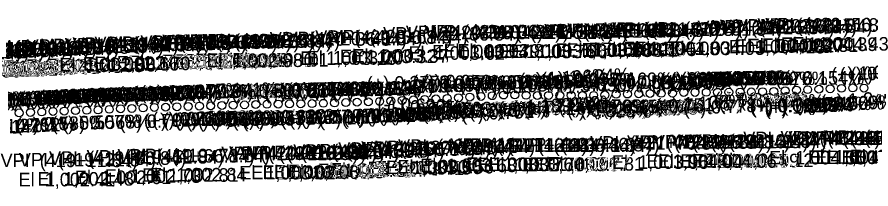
# Model space of a CAD drawing. Extents: x 16972137 to 16976972, y 12558490 to 12559551.
# Drawn here: x 16976278.8 to 16976657.8, y 12558916.8 to 12558992.8 of the extents above; entities that cross this region are included whole.
import ezdxf

# ---------------------------------------------------------------- set-up
doc = ezdxf.new("R2010")
doc.units = 0
doc.layers.add('RD_DDB_GradeTX', color=7, linetype='Continuous')
doc.layers.add('RD_DDB_PI', color=7, linetype='Continuous')

msp = doc.modelspace()

# ---------------------------------------------------------------- linework, layer by layer
at = {"layer": 'RD_DDB_PI'}
for centre in [(16976499.74, 12558958.35), (16976544.74, 12558958.62), (16976549.74, 12558958.74), (16976554.74, 12558958.85), (16976559.74, 12558958.96), (16976564.74, 12558959.04), (16976569.74, 12558959.11), (16976574.74, 12558959.45), (16976579.74, 12558959.47), (16976584.74, 12558959.49), (16976589.74, 12558959.51), (16976594.74, 12558959.56), (16976599.74, 12558959.59), (16976604.74, 12558959.68), (16976609.74, 12558959.79), (16976614.74, 12558959.91), (16976619.74, 12558960.22), (16976624.74, 12558960.48), (16976629.74, 12558960.68), (16976634.74, 12558960.88), (16976639.74, 12558961.08), (16976644.74, 12558961.27), (16976649.74, 12558961.46), (16976654.74, 12558961.37), (16976414.74, 12558954.64), (16976419.74, 12558954.78), (16976424.74, 12558954.95), (16976429.74, 12558955.13), (16976434.74, 12558955.3), (16976439.74, 12558955.47), (16976444.74, 12558955.67), (16976449.74, 12558955.93), (16976454.74, 12558956.15), (16976459.74, 12558956.36), (16976464.74, 12558956.58), (16976469.74, 12558956.79), (16976474.74, 12558957.09), (16976479.74, 12558957.39), (16976484.74, 12558957.69), (16976489.74, 12558958), (16976494.74, 12558958.29), (16976504.74, 12558958.18), (16976509.74, 12558958.1), (16976514.74, 12558958.11), (16976519.74, 12558958.13), (16976524.74, 12558958.12), (16976529.74, 12558958.09), (16976534.74, 12558958.15), (16976539.74, 12558958.34), (16976289.74, 12558950.83), (16976294.74, 12558951.03), (16976299.74, 12558951.2), (16976304.74, 12558951.38), (16976309.74, 12558951.58), (16976314.74, 12558951.7), (16976319.74, 12558951.96), (16976324.74, 12558952.21), (16976329.74, 12558952.38), (16976334.74, 12558952.6), (16976339.74, 12558952.81), (16976344.74, 12558952.94), (16976349.74, 12558953.11), (16976354.74, 12558953.26), (16976359.74, 12558953.39), (16976364.74, 12558953.53), (16976369.74, 12558953.68), (16976374.74, 12558953.83), (16976379.74, 12558953.96), (16976384.74, 12558954.1), (16976389.74, 12558954.2), (16976394.74, 12558954.3), (16976399.74, 12558954.37), (16976404.74, 12558954.44), (16976409.74, 12558954.53), (16976279.74, 12558950.37), (16976284.74, 12558950.61)]:
    msp.add_circle(centre, 1.75, dxfattribs=at)

# ---------------------------------------------------------------- texts
at = {"layer": 'RD_DDB_GradeTX'}
for s, rotation, p in [('(+) 1.040%', 2.9768, (16976640.33, 12558964.3)), ('(+) 0.798%', 2.2855, (16976644.02, 12558964.26)), ('(+) 0.788%', 2.2566, (16976648.9, 12558964.44)), ('(+) 0.778%', 2.2276, (16976654.2, 12558964.64)), ('(+) 1.196%', 3.4227, (16976502.06, 12558961.74)), ('(+) 1.124%', 3.2161, (16976511.72, 12558962.24)), ('(+) 0.092%', 0.2624, (16976513.61, 12558962.17)), ('(+) 0.277%', 0.7937, (16976514.05, 12558961.55)), ('(+) 0.169%', 0.4835, (16976530.6, 12558962.01)), ('(+) 1.040%', 2.9768, (16976560.44, 12558960.15)), ('(+) 0.798%', 2.2855, (16976564.08, 12558961.07)), ('(+) 0.470%', 1.3471, (16976564.07, 12558962.08)), ('(+) 0.448%', 1.2819, (16976568.9, 12558962.17)), ('(+) 0.788%', 2.2566, (16976568.97, 12558961.29)), ('(+) 0.425%', 1.2167, (16976573.43, 12558962.25)), ('(+) 0.358%', 1.0258, (16976578.27, 12558962.29)), ('(+) 0.787%', 2.2525, (16976579.26, 12558961.7)), ('(+) 0.265%', 0.7604, (16976583.46, 12558962.29)), ('(+) 0.740%', 2.12, (16976584.08, 12558962.03)), ('(+) 0.092%', 0.2624, (16976593.61, 12558962.53)), ('(+) 0.076%', 0.2168, (16976599.14, 12558962.54)), ('(+) 0.154%', 0.4413, (16976615.37, 12558962.71)), ('(+) 0.841%', 2.4083, (16976355.36, 12558956.47)), ('(+) 0.863%', 2.4706, (16976388.49, 12558956.29)), ('(+) 0.572%', 1.6372, (16976388.58, 12558957.22)), ('(+) 0.551%', 1.5767, (16976395.06, 12558957.39)), ('(+) 0.548%', 1.5691, (16976398.65, 12558957.48)), ('(+) 0.400%', 1.1454, (16976403.79, 12558957.48)), ('(+) 0.391%', 1.1187, (16976410.15, 12558957.6)), ('(+) 0.284%', 0.8126, (16976413.57, 12558957.57)), ('(+) 1.211%', 3.465, (16976418.39, 12558956.69)), ('(+) 0.268%', 0.7673, (16976418.58, 12558957.62)), ('(+) 1.242%', 3.5532, (16976424.98, 12558956.99)), ('(+) 1.124%', 3.2161, (16976431.86, 12558957.76)), ('(+) 0.277%', 0.7937, (16976434.06, 12558960.44)), ('(+) 0.684%', 1.9574, (16976448.86, 12558958.79)), ('(+) 0.657%', 1.8825, (16976453.92, 12558958.93)), ('(+) 0.067%', 0.1931, (16976454.14, 12558960.91)), ('(-) 0.056%', 359.8391, (16976458.75, 12558961.3)), ('(+) 0.863%', 2.4706, (16976468.41, 12558959.74)), ('(+) 0.851%', 2.4373, (16976475.13, 12558960.02)), ('(+) 1.108%', 3.1702, (16976481.97, 12558958.15)), ('(+) 0.470%', 1.3471, (16976484.1, 12558960.19)), ('(+) 0.448%', 1.2819, (16976488.92, 12558960.38)), ('(+) 0.425%', 1.2167, (16976493.45, 12558960.55)), ('(+) 0.358%', 1.0258, (16976498.28, 12558960.86)), ('(+) 1.342%', 3.84, (16976509.92, 12558958.1)), ('(-) 0.690%', 358.0253, (16976519.07, 12558960.69)), ('(-) 0.056%', 359.8391, (16976538.75, 12558961.08)), ('(-) 0.088%', 359.7485, (16976543.75, 12558961.03)), ('(+) 1.245%', 3.5629, (16976555.09, 12558959.21)), ('(+) 1.398%', 3.9989, (16976244.95, 12558951.58)), ('(+) 1.271%', 3.6374, (16976266.87, 12558952.8)), ('(+) 0.850%', 2.4346, (16976268.55, 12558952.79)), ('(+) 1.245%', 3.5625, (16976269.93, 12558952.97)), ('(+) 0.841%', 2.4083, (16976275.44, 12558953.11)), ('(+) 1.191%', 3.407, (16976278.6, 12558953.45)), ('(+) 1.104%', 3.1607, (16976281.96, 12558953.55)), ('(+) 0.690%', 1.9757, (16976283.91, 12558953.84)), ('(+) 1.100%', 3.147, (16976286.85, 12558953.81)), ('(+) 0.586%', 1.6795, (16976288.68, 12558954.32)), ('(+) 1.015%', 2.9063, (16976291.75, 12558953.99)), ('(+) 0.983%', 2.8136, (16976293.39, 12558954.04)), ('(+) 0.953%', 2.7275, (16976298.28, 12558954.25)), ('(+) 0.620%', 1.7751, (16976303.56, 12558954.63)), ('(+) 0.915%', 2.619, (16976305.23, 12558954.55)), ('(+) 0.572%', 1.6372, (16976308.62, 12558954.94)), ('(+) 0.768%', 2.1989, (16976309.02, 12558954.58)), ('(+) 0.703%', 2.0127, (16976313.62, 12558954.69)), ('(+) 0.551%', 1.5767, (16976315.1, 12558955.19)), ('(+) 0.548%', 1.5691, (16976318.68, 12558955.29)), ('(+) 0.698%', 1.9992, (16976318.86, 12558954.87)), ('(+) 0.400%', 1.1454, (16976323.81, 12558955.88)), ('(+) 0.391%', 1.1187, (16976330.17, 12558956.04)), ('(+) 0.514%', 1.4734, (16976330.31, 12558955.11)), ('(+) 0.284%', 0.8126, (16976333.58, 12558956.43)), ('(+) 0.977%', 2.7964, (16976339.28, 12558955.92)), ('(+) 0.712%', 2.038, (16976345.33, 12558955.94)), ('(+) 0.535%', 1.5325, (16976358.12, 12558956.3)), ('(+) 0.736%', 2.1075, (16976363.79, 12558955.71)), ('(+) 0.586%', 1.6795, (16976368.64, 12558956.67)), ('(+) 0.684%', 1.9574, (16976368.91, 12558956.05)), ('(+) 0.507%', 1.4514, (16976373.83, 12558956.74)), ('(+) 1.022%', 2.9245, (16976384.85, 12558955.62)), ('(+) 1.245%', 3.5629, (16976635.67, 12558952.2)), ('(+) 0.792%', 2.2674, (16976243.85, 12558951.97)), ('(+) 1.117%', 3.1973, (16976253.79, 12558951.85)), ('(+) 1.033%', 2.9562, (16976254.73, 12558951.61)), ('(+) 0.977%', 2.7964, (16976259.38, 12558952.02)), ('(-) 0.690%', 358.0253, (16976438.7, 12558951.45)), ('(-) 0.325%', 359.0691, (16976442.95, 12558950.19)), ('(+) 1.189%', 3.4011, (16976492.66, 12558949.14)), ('(+) 1.211%', 3.465, (16976498.96, 12558949.54)), ('(+) 1.242%', 3.5532, (16976505.56, 12558949.97)), ('(+) 0.076%', 0.2168, (16976519.19, 12558950.24)), ('(+) 0.099%', 0.2848, (16976524.02, 12558950.19)), ('(+) 0.154%', 0.4413, (16976535.46, 12558950.1)), ('(+) 0.751%', 2.1499, (16976555.89, 12558949.94)), ('(+) 1.108%', 3.1702, (16976562.51, 12558950.59)), ('(+) 0.778%', 2.2276, (16976574.73, 12558949.54)), ('(-) 0.345%', 359.0114, (16976588.3, 12558953.52)), ('(+) 1.342%', 3.84, (16976590.53, 12558951.49)), ('(-) 0.330%', 359.0559, (16976593.01, 12558953.39)), ('(-) 0.313%', 359.1044, (16976599.67, 12558953.23)), ('(+) 0.099%', 0.2848, (16976604.02, 12558950.58)), ('(+) 0.704%', 2.0164, (16976604.51, 12558950.08)), ('(+) 1.028%', 2.9425, (16976610.7, 12558949.34)), ('(+) 0.169%', 0.4835, (16976610.7, 12558950.69)), ('(+) 0.362%', 1.0383, (16976618.48, 12558950.93)), ('(+) 0.406%', 1.1637, (16976624.15, 12558951.08)), ('(+) 0.509%', 1.4584, (16976628.96, 12558951.27)), ('(+) 0.877%', 2.51, (16976404.78, 12558944.94)), ('(+) 1.189%', 3.4011, (16976412.81, 12558944.4)), ('(+) 1.196%', 3.4227, (16976422.93, 12558944.98)), ('(+) 0.392%', 1.1218, (16976423.5, 12558945.8)), ('(+) 0.403%', 1.1545, (16976428.74, 12558945.92)), ('(+) 0.580%', 1.6604, (16976433.87, 12558946.19)), ('(+) 0.665%', 1.9052, (16976439.14, 12558946.42)), ('(+) 0.736%', 2.1075, (16976444.17, 12558946.66)), ('(+) 0.045%', 0.1295, (16976448.76, 12558948.96)), ('(+) 0.835%', 2.3896, (16976458.68, 12558947.25)), ('(-) 0.088%', 359.7485, (16976463.7, 12558949.38)), ('(+) 1.022%', 2.9245, (16976465.35, 12558947.72)), ('(+) 0.248%', 0.709, (16976468.74, 12558948.34)), ('(+) 0.751%', 2.1499, (16976475.95, 12558946.94)), ('(+) 0.870%', 2.4914, (16976479.41, 12558948.21)), ('(+) 0.877%', 2.51, (16976484.7, 12558948.44)), ('(+) 0.265%', 0.7604, (16976503.63, 12558949.23)), ('(-) 0.325%', 359.0691, (16976522.94, 12558948.89)), ('(+) 0.045%', 0.1295, (16976528.76, 12558949.14)), ('(+) 0.067%', 0.1931, (16976534.18, 12558949.18)), ('(+) 0.362%', 1.0383, (16976538.5, 12558949.48)), ('(+) 0.406%', 1.1637, (16976544.17, 12558949.45)), ('(+) 0.248%', 0.709, (16976548.73, 12558949.33)), ('(+) 0.509%', 1.4584, (16976548.99, 12558949.24)), ('(+) 1.276%', 3.6497, (16976261.1, 12558940.42)), ('(+) 0.535%', 1.5325, (16976278.47, 12558942.16)), ('(+) 0.507%', 1.4514, (16976294.16, 12558942.72)), ('(+) 0.568%', 1.626, (16976299.02, 12558942.66)), ('(+) 0.792%', 2.2674, (16976324.26, 12558943.14)), ('(+) 1.033%', 2.9562, (16976335.24, 12558943.75)), ('(+) 0.268%', 0.7673, (16976338.75, 12558944.55)), ('(+) 0.392%', 1.1218, (16976343.51, 12558944.24)), ('(+) 0.403%', 1.1545, (16976348.75, 12558944.3)), ('(+) 0.850%', 2.4346, (16976348.98, 12558944.19)), ('(+) 0.580%', 1.6604, (16976353.91, 12558943.87)), ('(+) 0.665%', 1.9052, (16976359.19, 12558943.76)), ('(+) 0.690%', 1.9757, (16976364.27, 12558944.61)), ('(+) 0.657%', 1.8825, (16976374.36, 12558944.31)), ('(+) 0.835%', 2.3896, (16976378.76, 12558943.91)), ('(+) 0.568%', 1.626, (16976378.99, 12558944.93)), ('(+) 0.620%', 1.7751, (16976383.89, 12558945.12)), ('(+) 0.851%', 2.4373, (16976395.71, 12558944.62)), ('(+) 0.870%', 2.4914, (16976399.49, 12558944.73)), ('(+) 0.514%', 1.4734, (16976250.64, 12558941.05)), ('(+) 1.142%', 3.2679, (16976257.4, 12558940.07)), ('(+) 0.712%', 2.038, (16976265.81, 12558941.1))]:
    msp.add_text(s, height=6, rotation=rotation, dxfattribs=at).set_placement(p)
at = {"layer": 'RD_DDB_PI'}
for s, p in [('VPI  (421+81.84)', (16976539.46, 12558984.45)), ('VPI  (421+86.84)', (16976542.92, 12558984.47)), ('VPI  (422+01.84)', (16976557.57, 12558984.56)), ('VPI  (422+26.84)', (16976580.79, 12558985.22)), ('VPI  (422+31.84)', (16976587.27, 12558985.48)), ('VPI  (422+36.84)', (16976590.74, 12558985.68)), ('VPI  (422+41.84)', (16976597.68, 12558985.88)), ('VPI  (422+51.84)', (16976607.45, 12558986.27)), ('VPI  (422+56.84)', (16976610.91, 12558986.46)), ('VPI  (420+56.84)', (16976411.15, 12558980.93)), ('VPI  (420+61.84)', (16976417.92, 12558981.15)), ('VPI  (420+86.84)', (16976441.27, 12558982.39)), ('VPI  (420+96.84)', (16976451.39, 12558983)), ('VPI  (421+01.84)', (16976459.46, 12558983.29)), ('VPI  (421+06.84)', (16976462.92, 12558983.35)), ('VPI  (421+26.84)', (16976482.68, 12558983.13)), ('VPI  (421+31.84)', (16976489.16, 12558983.12)), ('VPI  (421+51.84)', (16976509.34, 12558983.62)), ('VPI  (421+56.84)', (16976512.8, 12558983.74)), ('VPI  (421+61.84)', (16976519.57, 12558983.85)), ('VPI  (421+66.84)', (16976523.04, 12558983.96)), ('VPI  (421+71.84)', (16976529.75, 12558984.04)), ('VPI  (419+16.84)', (16976274.93, 12558976.58)), ('VPI  (419+26.84)', (16976283.04, 12558976.96)), ('VPI  (419+31.84)', (16976289.51, 12558977.21)), ('VPI  (419+41.84)', (16976299.93, 12558977.6)), ('VPI  (419+46.84)', (16976303.39, 12558977.81)), ('VPI  (419+56.84)', (16976313.16, 12558978.11)), ('VPI  (419+61.84)', (16976319.93, 12558978.26)), ('VPI  (419+76.84)', (16976333.57, 12558978.68)), ('VPI  (419+81.84)', (16976339.81, 12558978.83)), ('VPI  (419+86.84)', (16976343.27, 12558978.96)), ('VPI  (419+91.84)', (16976349.93, 12558979.1)), ('VPI  (419+96.84)', (16976353.39, 12558979.2)), ('VPI  (420+01.84)', (16976357.8, 12558979.3)), ('VPI  (420+06.84)', (16976361.27, 12558979.37)), ('VPI  (420+36.84)', (16976390.97, 12558980.13)), ('VPI  (420+41.84)', (16976397.92, 12558980.3)), ('El  1,004.18', (16976594.73, 12558976.72)), ('El  1,004.23', (16976597.55, 12558976.98)), ('El  1,004.27', (16976603.11, 12558977.18)), ('El  1,004.31', (16976609.41, 12558977.38)), ('El  1,004.39', (16976617.87, 12558977.77)), ('El  1,004.43', (16976622.9, 12558977.96)), ('VPI  (418+61.84)', (16976219.81, 12558974.02)), ('VPI  (418+66.84)', (16976223.27, 12558974.32)), ('VPI  (418+71.84)', (16976229.99, 12558974.59)), ('VPI  (418+76.84)', (16976233.45, 12558974.87)), ('VPI  (418+81.84)', (16976239.69, 12558975.12)), ('VPI  (418+86.84)', (16976243.16, 12558975.37)), ('VPI  (418+91.84)', (16976249.81, 12558975.61)), ('VPI  (418+96.84)', (16976253.27, 12558975.83)), ('VPI  (419+01.84)', (16976259.81, 12558976.03)), ('VPI  (419+06.84)', (16976263.27, 12558976.2)), ('El  1,003.62', (16976452.55, 12558973.89)), ('El  1,003.74', (16976463.05, 12558974.5)), ('El  1,003.79', (16976468.05, 12558974.79)), ('El  1,003.81', (16976474.29, 12558974.85)), ('El  1,003.76', (16976493.05, 12558974.63)), ('El  1,003.76', (16976498.05, 12558974.62)), ('El  1,003.86', (16976517.75, 12558975.12)), ('El  1,003.88', (16976522.66, 12558975.24)), ('El  1,003.91', (16976529.41, 12558975.35)), ('El  1,003.93', (16976532.49, 12558975.46)), ('El  1,003.95', (16976537.66, 12558975.54)), ('El  1,004.03', (16976547.78, 12558975.95)), ('El  1,004.03', (16976552.78, 12558975.97)), ('El  1,004.05', (16976567.96, 12558976.06)), ('El  1,002.66', (16976307.93, 12558969.1)), ('El  1,002.70', (16976312.99, 12558969.31)), ('El  1,002.76', (16976323.11, 12558969.61)), ('El  1,002.79', (16976328.11, 12558969.76)), ('El  1,002.87', (16976342.99, 12558970.18)), ('El  1,002.90', (16976347.81, 12558970.33)), ('El  1,002.93', (16976352.55, 12558970.46)), ('El  1,002.96', (16976357.93, 12558970.6)), ('El  1,002.98', (16976362.84, 12558970.7)), ('El  1,003.00', (16976367.64, 12558970.8)), ('El  1,003.01', (16976374.29, 12558970.87)), ('El  1,003.16', (16976404.41, 12558971.63)), ('El  1,003.20', (16976407.4, 12558971.8)), ('El  1,003.32', (16976422.13, 12558972.43)), ('El  1,003.37', (16976427.64, 12558972.65)), ('El  1,002.06', (16976237.81, 12558966.09)), ('El  1,002.11', (16976246, 12558966.37)), ('El  1,002.16', (16976249.47, 12558966.62)), ('El  1,002.21', (16976254.11, 12558966.87)), ('El  1,002.26', (16976257.58, 12558967.11)), ('El  1,002.30', (16976262.4, 12558967.33)), ('El  1,002.34', (16976267.52, 12558967.53)), ('El  1,002.38', (16976272.43, 12558967.7)), ('El  1,002.45', (16976282.72, 12558968.08)), ('El  1,002.53', (16976292.31, 12558968.46)), ('El  1,002.58', (16976297.61, 12558968.71)), ('VPI  (422+21.84)', (16976577.33, 12558934.91)), ('VPI  (422+46.84)', (16976601.15, 12558936.08)), ('VPI  (422+61.84)', (16976617.68, 12558936.37)), ('VPI  (422+66.84)', (16976621.15, 12558936.29)), ('VPI  (422+71.84)', (16976627.86, 12558936.21)), ('VPI  (422+76.84)', (16976631.33, 12558936.39)), ('VPI  (422+81.84)', (16976637.57, 12558936.64)), ('VPI  (420+66.84)', (16976421.39, 12558931.36)), ('VPI  (420+71.84)', (16976428.1, 12558931.58)), ('VPI  (420+76.84)', (16976431.56, 12558931.79)), ('VPI  (420+81.84)', (16976437.8, 12558932.09)), ('VPI  (420+91.84)', (16976447.92, 12558932.69)), ('VPI  (421+11.84)', (16976471.11, 12558933.18)), ('VPI  (421+16.84)', (16976474.57, 12558933.1)), ('VPI  (421+21.84)', (16976479.22, 12558933.11)), ('VPI  (421+36.84)', (16976492.63, 12558933.09)), ('VPI  (421+41.84)', (16976499.57, 12558933.15)), ('VPI  (421+46.84)', (16976503.04, 12558933.34)), ('VPI  (421+76.84)', (16976533.22, 12558934.11)), ('VPI  (421+91.84)', (16976549.57, 12558934.49)), ('VPI  (421+96.84)', (16976553.04, 12558934.51)), ('VPI  (422+06.84)', (16976561.03, 12558934.59)), ('VPI  (422+11.84)', (16976569.22, 12558934.68)), ('VPI  (422+16.84)', (16976572.68, 12558934.79)), ('VPI  (419+36.84)', (16976292.98, 12558927.38)), ('VPI  (419+51.84)', (16976309.69, 12558927.94)), ('VPI  (419+66.84)', (16976323.39, 12558928.39)), ('VPI  (419+71.84)', (16976330.11, 12558928.53)), ('VPI  (420+11.84)', (16976369.46, 12558929.44)), ('VPI  (420+16.84)', (16976372.92, 12558929.53)), ('VPI  (420+21.84)', (16976377.57, 12558929.64)), ('VPI  (420+26.84)', (16976381.03, 12558929.78)), ('VPI  (420+31.84)', (16976387.51, 12558929.95)), ('VPI  (420+46.84)', (16976401.39, 12558930.47)), ('VPI  (420+51.84)', (16976407.68, 12558930.67)), ('El  1,004.35', (16976612.66, 12558927.58)), ('El  1,004.41', (16976629.82, 12558927.87)), ('El  1,004.40', (16976633.17, 12558927.79)), ('El  1,004.38', (16976637.78, 12558927.71)), ('El  1,004.41', (16976644.82, 12558927.89)), ('El  1,004.47', (16976648.46, 12558928.14)), ('VPI  (419+11.84)', (16976271.46, 12558926.38)), ('VPI  (419+21.84)', (16976279.57, 12558926.7)), ('El  1,003.56', (16976447.64, 12558923.59)), ('El  1,003.68', (16976457.78, 12558924.19)), ('El  1,003.77', (16976478.23, 12558924.68)), ('El  1,003.76', (16976483.05, 12558924.6)), ('El  1,003.76', (16976488.05, 12558924.61)), ('El  1,003.76', (16976503.05, 12558924.59)), ('El  1,003.77', (16976508.23, 12558924.65)), ('El  1,003.81', (16976514.29, 12558924.84)), ('El  1,003.96', (16976542.87, 12558925.61)), ('El  1,004.04', (16976558.17, 12558925.99)), ('El  1,004.04', (16976563.17, 12558926.01)), ('El  1,004.06', (16976573.17, 12558926.09)), ('El  1,004.07', (16976578.34, 12558926.18)), ('El  1,004.09', (16976583.17, 12558926.29)), ('El  1,004.12', (16976589.5, 12558926.41)), ('El  1,002.81', (16976334.35, 12558919.89)), ('El  1,002.84', (16976337.81, 12558920.03)), ('El  1,003.02', (16976377.43, 12558920.94)), ('El  1,003.04', (16976382.75, 12558921.03)), ('El  1,003.06', (16976387.75, 12558921.14)), ('El  1,003.09', (16976392.75, 12558921.28)), ('El  1,003.13', (16976399.02, 12558921.45)), ('El  1,003.23', (16976412.13, 12558921.97)), ('El  1,003.27', (16976417.69, 12558922.17)), ('El  1,003.41', (16976434.41, 12558922.86)), ('El  1,003.45', (16976437.66, 12558923.08)), ('El  1,003.50', (16976442.52, 12558923.29)), ('El  1,002.41', (16976279.47, 12558917.88)), ('El  1,002.48', (16976287.84, 12558918.2)), ('El  1,002.61', (16976304.47, 12558918.88)), ('El  1,002.73', (16976317.72, 12558919.44))]:
    msp.add_text(s, height=6, dxfattribs=at).set_placement(p)

doc.saveas('drawing.dxf')
